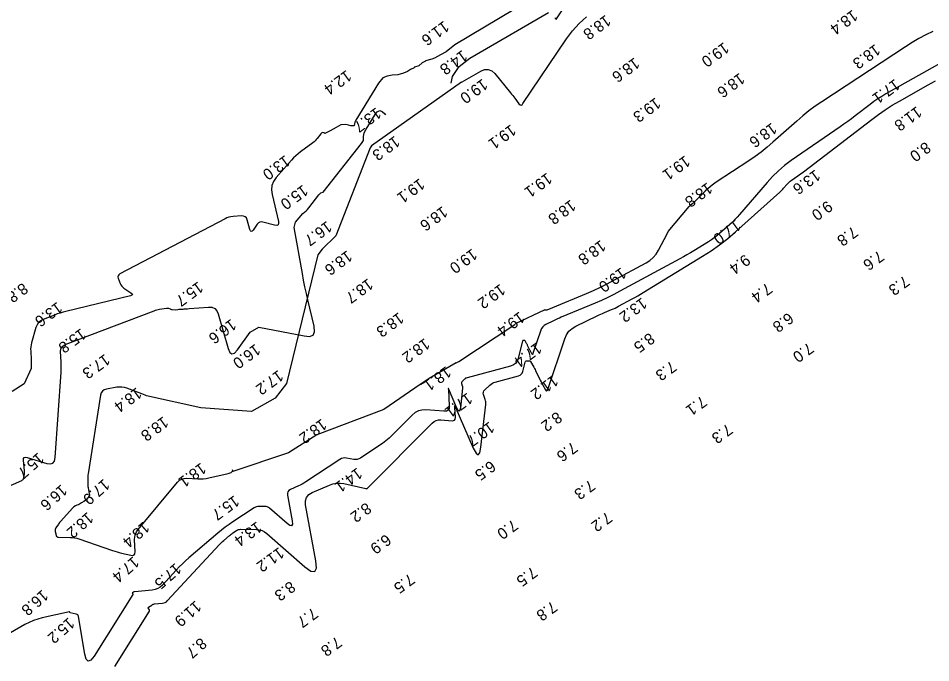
# Model space of a CAD drawing. Extents: x 824616 to 827440, y 158441 to 163197.
# Drawn here: x 825792.9 to 826199.3, y 159276.7 to 159563.5 of the extents above; entities that cross this region are included whole.
import ezdxf

# ---------------------------------------------------------------- set-up
doc = ezdxf.new("R2010")
doc.units = 0
for name, color, linetype in [('V-CHAN-CONT-EL14', 7, 'Continuous'), ('V-CHAN-CONT-EL16', 7, 'Continuous'), ('V-CHAN-CONT-EL18', 7, 'Continuous'), ('V-TOPO-SOUN', 7, 'Continuous')]:
    doc.layers.add(name, color=color, linetype=linetype)

msp = doc.modelspace()

# ---------------------------------------------------------------- linework, layer by layer
at = {"layer": 'V-CHAN-CONT-EL14'}
for points in [[(826013.71, 159567.36), (825987.36, 159551.67), (825983.43, 159548.57), (825981.02, 159547.23), (825979.59, 159546.5), (825978.35, 159545.74), (825977.08, 159545.37), (825974.32, 159544.63), (825974.34, 159544.36), (825972.76, 159543.67), (825971.35, 159542.4), (825969.32, 159541.75), (825969.24, 159541.53), (825967.6, 159540.72), (825966.32, 159539.89), (825964.52, 159539.13), (825961.94, 159538.36), (825959.37, 159538.16), (825957.28, 159537.82), (825955.28, 159536.97), (825953.37, 159534.66), (825943.28, 159518.21), (825942.85, 159517.32), (825942.63, 159516.42), (825942.61, 159516.18), (825942.57, 159515.99), (825942.51, 159515.83), (825942.35, 159515.71), (825942.05, 159515.63), (825941.67, 159515.58), (825940.99, 159515.66), (825940, 159516), (825938.85, 159516.3), (825936.61, 159516.12), (825934.55, 159514.97), (825931.88, 159513.39), (825929.43, 159512.2), (825928.99, 159512.58), (825928.55, 159512.69), (825928.13, 159512.55), (825927.71, 159512.14), (825926.06, 159510.01), (825925.63, 159509.49), (825925.17, 159509.01), (825924.67, 159508.56), (825924.15, 159508.14), (825918.64, 159504.07), (825917.57, 159503.24), (825916.55, 159502.34), (825915.57, 159501.4), (825914.65, 159500.4), (825907.83, 159492.63), (825906.63, 159490.93), (825905.92, 159489.11), (825905.7, 159487.18), (825905.96, 159485.12), (825908.8, 159473.1), (825908.89, 159472.15), (825908.64, 159471.55), (825908.03, 159471.31), (825907.08, 159471.42), (825901.86, 159472.79), (825901.12, 159472.89), (825900.46, 159472.77), (825899.88, 159472.44), (825899.37, 159471.89), (825897.5, 159469.26), (825897.06, 159468.78), (825896.69, 159468.67), (825896.37, 159468.9), (825896.12, 159469.5), (825894.86, 159473.87), (825894.51, 159474.67), (825893.98, 159475.21), (825893.29, 159475.51), (825892.42, 159475.57), (825888.61, 159475.3), (825887.67, 159475.18), (825886.76, 159474.97), (825885.87, 159474.67), (825885.01, 159474.27), (825838.16, 159449.73), (825837.68, 159449.39), (825837.4, 159448.96), (825837.33, 159448.46), (825837.46, 159447.88), (825838.39, 159445.41), (825838.66, 159444.83), (825839.01, 159444.3), (825839.44, 159443.84), (825839.96, 159443.45), (825843.11, 159441.36), (825843.62, 159440.92), (825843.76, 159440.56), (825843.51, 159440.25), (825842.87, 159440.02), (825814.2, 159433.05), (825812.9, 159432.71), (825811.62, 159432.33), (825810.34, 159431.91), (825809.08, 159431.45), (825804.07, 159429.51), (825802.93, 159428.93), (825802, 159428.14), (825801.3, 159427.15), (825800.83, 159425.96), (825798.89, 159419.14), (825798.67, 159418.2), (825798.52, 159417.26), (825798.46, 159416.3), (825798.47, 159415.34), (825798.69, 159411.46), (825798.73, 159410.5), (825798.74, 159409.53), (825798.72, 159408.56), (825798.67, 159407.59), (825795.5, 159400.82), (825790.27, 159397.45)], [(825835.93, 159275.06), (825851.33, 159299.67), (825851.4, 159299.82), (825851.43, 159299.97), (825851.4, 159300.13), (825851.32, 159300.27), (825850.91, 159300.87), (825850.83, 159301.01), (825850.83, 159301.15), (825850.88, 159301.27), (825850.99, 159301.38), (825852.4, 159302.39), (825852.69, 159302.57), (825853, 159302.71), (825853.32, 159302.8), (825853.66, 159302.86), (825857.11, 159303.18), (825857.77, 159303.3), (825858.38, 159303.54), (825858.93, 159303.88), (825859.43, 159304.33), (825882.36, 159329.15), (825882.86, 159329.67), (825883.38, 159330.18), (825883.91, 159330.67), (825884.45, 159331.15), (825887.02, 159333.34), (825887.39, 159333.65), (825887.78, 159333.94), (825888.16, 159334.23), (825888.56, 159334.5), (825890.17, 159335.56), (825890.59, 159335.79), (825891.02, 159335.96), (825891.47, 159336.05), (825891.94, 159336.08), (825898.98, 159336), (825900.27, 159335.88), (825901.48, 159335.54), (825902.61, 159334.99), (825903.65, 159334.22), (825920.6, 159319.39), (825923.27, 159317.49), (825924.97, 159317.31), (825925.68, 159318.85), (825925.42, 159322.12), (825920.9, 159347.03), (825920.82, 159348.81), (825921.28, 159350.31), (825922.27, 159351.52), (825923.8, 159352.45), (825931.48, 159355.79), (825933.04, 159356.33), (825934.64, 159356.62), (825936.26, 159356.64), (825937.9, 159356.41), (825947.77, 159354.23), (825947.81, 159354.22), (825947.85, 159354.21), (825947.89, 159354.2), (825947.93, 159354.19), (825948.18, 159354.15), (825948.18, 159354.15), (825948.18, 159354.15), (825948.18, 159354.15), (825948.19, 159354.15), (825948.2, 159354.16), (825948.2, 159354.16), (825977.32, 159383.38), (825978.13, 159384.05), (825979.03, 159384.51), (825980.01, 159384.75), (825981.07, 159384.78), (825986.12, 159384.41), (825986.79, 159384.45), (825987.26, 159384.71), (825987.53, 159385.17), (825987.59, 159385.85), (825987.34, 159390.33), (825987.34, 159390.42), (825987.33, 159390.52), (825987.33, 159390.61), (825987.32, 159390.7), (825987.3, 159391.07), (825987.3, 159391.14), (825987.31, 159391.16), (825987.33, 159391.14), (825987.36, 159391.08), (825995.56, 159372.19), (825996.78, 159369.91), (825997.76, 159369.23), (825998.49, 159370.16), (825998.98, 159372.71), (826001.07, 159391.61), (826001.1, 159392.19), (826001.08, 159392.76), (826000.99, 159393.33), (826000.84, 159393.9), (826000.12, 159396.14), (826000.02, 159396.68), (826000.07, 159397.18), (826000.27, 159397.64), (826000.62, 159398.07), (826002.92, 159400.24), (826003.47, 159400.69), (826004.06, 159401.07), (826004.69, 159401.38), (826005.37, 159401.6), (826015.67, 159404.36), (826016.38, 159404.64), (826016.94, 159405.07), (826017.36, 159405.63), (826017.63, 159406.34), (826018.7, 159410.53), (826018.78, 159410.74), (826018.92, 159410.9), (826019.1, 159411), (826019.32, 159411.04), (826020.32, 159411.1), (826020.56, 159411.09), (826020.76, 159411.02), (826020.93, 159410.89), (826021.07, 159410.7), (826022.5, 159408.17), (826022.77, 159407.67), (826023.04, 159407.17), (826023.3, 159406.66), (826023.56, 159406.15), (826025.1, 159403.01), (826025.4, 159402.39), (826025.71, 159401.79), (826026.02, 159401.18), (826026.34, 159400.58), (826027.64, 159398.18), (826027.95, 159397.74), (826028.23, 159397.61), (826028.48, 159397.79), (826028.71, 159398.28), (826036.27, 159420.84), (826037.07, 159422.65), (826038.17, 159424.2), (826039.56, 159425.48), (826041.26, 159426.51), (826050.75, 159431.09), (826051.54, 159431.46), (826052.33, 159431.82), (826053.12, 159432.17), (826053.92, 159432.52), (826057.13, 159433.85), (826057.93, 159434.2), (826058.72, 159434.56), (826059.5, 159434.95), (826060.27, 159435.35), (826066.28, 159438.61), (826067.54, 159439.3), (826068.78, 159440), (826070.01, 159440.72), (826071.24, 159441.46), (826097.63, 159457.6), (826101.5, 159460.08), (826105.24, 159462.74), (826108.86, 159465.55), (826112.35, 159468.54), (826132.04, 159486.13), (826132.48, 159486.54), (826132.92, 159486.97), (826133.34, 159487.41), (826133.74, 159487.86), (826135.33, 159489.71), (826135.74, 159490.16), (826136.17, 159490.58), (826136.63, 159490.97), (826137.12, 159491.33), (826140.02, 159493.33), (826140.66, 159493.78), (826141.31, 159494.24), (826141.94, 159494.71), (826142.57, 159495.18), (826172.98, 159518.53), (826175.95, 159520.73), (826178.99, 159522.82), (826182.1, 159524.8), (826185.28, 159526.67), (826198.15, 159533.93), (826201.38, 159535.74)]]:
    msp.add_lwpolyline(points, dxfattribs=at)
at = {"layer": 'V-CHAN-CONT-EL16'}
for points in [[(826031.92, 159563.69), (826032.27, 159563.21), (826032.36, 159563.12), (826032.45, 159563.09), (826032.54, 159563.12), (826032.62, 159563.22), (826036.19, 159568.54)], [(825985.65, 159534.6), (825986.29, 159537.62), (825989.25, 159542.11), (825994.07, 159545.82), (826028.98, 159566.02)], [(826224.18, 159555.16), (826179.28, 159529.82), (826177.47, 159528.75), (826175.7, 159527.63), (826173.98, 159526.44), (826172.29, 159525.2), (826165.64, 159520.09), (826163.96, 159518.82), (826162.27, 159517.57), (826160.57, 159516.35), (826158.85, 159515.15), (826137.13, 159500.17), (826134.2, 159498.01), (826131.43, 159495.67), (826128.81, 159493.16), (826126.36, 159490.47), (826114.07, 159476.15), (826113.06, 159475.01), (826112, 159473.9), (826110.91, 159472.82), (826109.79, 159471.78), (826105.21, 159467.69), (826104.05, 159466.7), (826102.84, 159465.76), (826101.59, 159464.87), (826100.3, 159464.05), (826093.75, 159460.04), (826092.22, 159459.11), (826090.67, 159458.21), (826089.11, 159457.33), (826087.54, 159456.46), (826060.84, 159442), (826058.15, 159440.59), (826055.42, 159439.24), (826052.66, 159437.97), (826049.87, 159436.76), (826034.76, 159430.46), (826033.89, 159430.09), (826033.03, 159429.71), (826032.17, 159429.32), (826031.32, 159428.91), (826027.92, 159427.27), (826027.14, 159426.8), (826026.49, 159426.21), (826025.99, 159425.5), (826025.62, 159424.66), (826022.13, 159414.26), (826022.03, 159414.03), (826021.91, 159413.95), (826021.78, 159414.01), (826021.64, 159414.21), (826021.04, 159415.32), (826020.89, 159415.6), (826020.75, 159415.87), (826020.61, 159416.15), (826020.47, 159416.44), (826019.76, 159417.89), (826019.64, 159418.12), (826019.52, 159418.36), (826019.4, 159418.59), (826019.27, 159418.82), (826018.61, 159419.98), (826018.54, 159420.07), (826018.47, 159420.13), (826018.37, 159420.16), (826018.26, 159420.17), (826017.8, 159420.14), (826017.7, 159420.12), (826017.62, 159420.08), (826017.55, 159420), (826017.52, 159419.9), (826015.52, 159412.12), (826015.06, 159410.9), (826014.35, 159409.93), (826013.39, 159409.21), (826012.18, 159408.73), (825992.76, 159403.53), (825992.45, 159403.42), (825992.15, 159403.28), (825991.88, 159403.11), (825991.63, 159402.9), (825990.57, 159401.9), (825990.41, 159401.7), (825990.32, 159401.49), (825990.29, 159401.26), (825990.34, 159401.01), (825990.67, 159399.97), (825990.74, 159399.72), (825990.78, 159399.45), (825990.79, 159399.19), (825990.78, 159398.92), (825989.82, 159390.21), (825989.59, 159389.04), (825989.25, 159388.61), (825988.8, 159388.92), (825988.24, 159389.97), (825984.46, 159398.68), (825984.44, 159398.71), (825984.43, 159398.72), (825984.43, 159398.7), (825984.43, 159398.67), (825984.44, 159398.5), (825984.44, 159398.46), (825984.45, 159398.42), (825984.45, 159398.37), (825984.45, 159398.33), (825984.85, 159390.92), (825984.75, 159389.84), (825984.33, 159389.09), (825983.57, 159388.68), (825982.49, 159388.6), (825974.39, 159389.2), (825972.69, 159389.16), (825971.11, 159388.77), (825969.67, 159388.03), (825968.35, 159386.95), (825959.42, 159377.98), (825958.04, 159376.67), (825956.6, 159375.43), (825955.09, 159374.26), (825953.53, 159373.17), (825945.31, 159367.76), (825944.61, 159367.39), (825943.89, 159367.16), (825943.13, 159367.09), (825942.35, 159367.17), (825939.15, 159367.78), (825938.36, 159367.86), (825937.61, 159367.78), (825936.88, 159367.56), (825936.19, 159367.19), (825920.97, 159357.16), (825920.17, 159356.66), (825919.35, 159356.19), (825918.51, 159355.76), (825917.66, 159355.37), (825914.2, 159353.86), (825913.46, 159353.41), (825912.98, 159352.83), (825912.76, 159352.11), (825912.8, 159351.25), (825914.87, 159339.86), (825914.99, 159338.36), (825914.66, 159337.65), (825913.88, 159337.73), (825912.65, 159338.6), (825904.84, 159345.43), (825904.36, 159345.79), (825903.84, 159346.04), (825903.29, 159346.2), (825902.69, 159346.25), (825900.23, 159346.28), (825899.63, 159346.25), (825899.06, 159346.12), (825898.51, 159345.91), (825897.98, 159345.62), (825888.54, 159339.4), (825886.81, 159338.22), (825885.13, 159336.99), (825883.48, 159335.72), (825881.87, 159334.39), (825868.92, 159323.36), (825867.45, 159322.07), (825866.02, 159320.73), (825864.63, 159319.35), (825863.27, 159317.93), (825857.12, 159311.28), (825856.15, 159310.39), (825855.07, 159309.72), (825853.88, 159309.27), (825852.59, 159309.03), (825844.75, 159308.3), (825844.63, 159308.28), (825844.51, 159308.24), (825844.4, 159308.19), (825844.3, 159308.13), (825843.79, 159307.76), (825843.75, 159307.72), (825843.73, 159307.68), (825843.73, 159307.63), (825843.76, 159307.58), (825843.91, 159307.36), (825843.93, 159307.31), (825843.95, 159307.25), (825843.94, 159307.2), (825843.91, 159307.14), (825826.74, 159279.7), (825825.29, 159277.86), (825824.12, 159277.38), (825823.22, 159278.27), (825822.59, 159280.53), (825819.79, 159297.25), (825819.66, 159297.67), (825819.44, 159297.99), (825819.13, 159298.23), (825818.72, 159298.38), (825816.11, 159298.97), (825816.06, 159298.99), (825816.01, 159299.02), (825815.98, 159299.06), (825815.96, 159299.11), (825815.9, 159299.34), (825815.87, 159299.39), (825815.84, 159299.42), (825815.8, 159299.43), (825815.75, 159299.43), (825803.63, 159296.68), (825801.62, 159296.15), (825799.66, 159295.47), (825797.76, 159294.66), (825795.91, 159293.69), (825784.78, 159287.37)], [(825945.71, 159507.78), (825946.6, 159509.14), (825946.61, 159510.88), (825947.02, 159512.58), (825947.82, 159514.22), (825951.8, 159520.71), (825952.81, 159521.95), (825953.88, 159522.4), (825955, 159522.08), (825956.17, 159520.99), (825956.53, 159520.54)], [(825915.81, 159470.47), (825916.37, 159472.8), (825919.7, 159476.61), (825920.41, 159477.18), (825921.08, 159477.79), (825921.71, 159478.44), (825922.29, 159479.14), (825926.74, 159484.9), (825927.68, 159485.8), (825928.64, 159486.13), (825945.71, 159507.78)], [(825900.11, 159426.08), (825920.25, 159422.14), (825922.7, 159421.84), (825924.26, 159422.46), (825924.91, 159424), (825924.67, 159426.46), (825921.91, 159438.14), (825921.24, 159441.07), (825920.61, 159444), (825920.02, 159446.94), (825919.47, 159449.9), (825915.81, 159470.47)], [(825767.31, 159346), (825794.49, 159357.87), (825794.82, 159358.06), (825795.08, 159358.31), (825795.26, 159358.62), (825795.37, 159358.99), (825795.67, 159360.58), (825795.72, 159360.98), (825795.76, 159361.37), (825795.76, 159361.77), (825795.74, 159362.18), (825795.31, 159366.8), (825795.34, 159367.56), (825795.62, 159368.02), (825796.13, 159368.2), (825796.88, 159368.08), (825805.64, 159365.39), (825807.19, 159365.15), (825808.33, 159365.5), (825809.06, 159366.44), (825809.39, 159367.97), (825812.03, 159406.07), (825812.09, 159407.21), (825812.12, 159408.35), (825812.11, 159409.49), (825812.06, 159410.63), (825811.8, 159415.19), (825811.88, 159416.24), (825812.24, 159417.11), (825812.88, 159417.79), (825813.81, 159418.29), (825853.52, 159433.36), (825854.08, 159433.56), (825854.66, 159433.73), (825855.24, 159433.87), (825855.83, 159433.99), (825858.98, 159434.52), (825859.18, 159434.54), (825859.38, 159434.54), (825859.58, 159434.51), (825859.77, 159434.45), (825860.54, 159434.16), (825860.73, 159434.09), (825860.91, 159433.99), (825861.18, 159433.95), (825861.53, 159433.84), (825862.83, 159433.81), (825864.05, 159433.93), (825864.52, 159434)], [(825864.41, 159434.01), (825864.63, 159433.99), (825865.48, 159434.02), (825866.32, 159434.1), (825866.89, 159434.16), (825867.41, 159434.17), (825867.92, 159434.18), (825868.34, 159434.22), (825869.11, 159434.38), (825877.59, 159434.99), (825879.15, 159434.89), (825880.4, 159434.35), (825881.34, 159433.37), (825881.97, 159431.93), (825886.39, 159416.62), (825887.15, 159414.83), (825888.1, 159414.12), (825889.22, 159414.47), (825890.54, 159415.91), (825896.15, 159423.78), (825900.11, 159426.08)]]:
    msp.add_lwpolyline(points, dxfattribs=at)
at = {"layer": 'V-CHAN-CONT-EL18'}
for p, q in [((826082.27, 159468.59), (826091.68, 159479.75)), ((826027.4, 159433.71), (826014.24, 159427.47))]:
    msp.add_line(p, q, dxfattribs=at)
for points in [[(825990.34, 159535.04), (825990.62, 159535.25), (825998.87, 159540.03), (826000.62, 159540.74), (826002.25, 159540.79), (826003.76, 159540.18), (826005.15, 159538.89), (826012.14, 159530.4), (826012.63, 159529.8), (826013.11, 159529.2), (826013.59, 159528.58), (826014.05, 159527.97), (826015.9, 159525.49), (826016.36, 159525.03), (826016.81, 159524.88), (826017.26, 159525.05), (826017.69, 159525.53), (826036.99, 159554.34), (826039.66, 159557.94), (826042.64, 159561.23), (826045.94, 159564.2)], [(826200.24, 159557.7), (826197.1, 159556.15), (826194.02, 159554.49), (826191, 159552.73), (826188.04, 159550.86), (826150.72, 159526.31), (826147.82, 159524.33), (826145.01, 159522.25), (826142.27, 159520.07), (826139.62, 159517.79), (826128.99, 159508.32), (826126.41, 159506.1), (826123.75, 159503.98), (826121.02, 159501.95), (826118.21, 159500.03), (826103.76, 159490.52), (826102.47, 159489.62), (826101.22, 159488.66), (826100.03, 159487.64), (826098.88, 159486.56), (826094.39, 159482.13), (826093.25, 159481.05), (826092.05, 159480.04), (826091.68, 159479.75)], [(825990.34, 159535.04), (825950.26, 159506.81), (825949.64, 159505.8), (825934.36, 159466.66), (825928.2, 159460.7), (825926.28, 159458.21), (825912.39, 159401), (825907.38, 159394.5), (825896.8, 159388.56), (825874.22, 159390.11), (825850.1, 159395.43)], [(826027.4, 159433.71), (826028.38, 159433.83), (826030.99, 159434.83), (826045.97, 159441.07), (826049.08, 159442.42), (826052.16, 159443.84), (826055.2, 159445.34), (826058.21, 159446.92), (826072.49, 159454.66), (826074.2, 159455.75), (826075.69, 159457.05), (826076.97, 159458.56), (826078.03, 159460.29), (826081.85, 159467.61), (826082.27, 159468.59)], [(825987.88, 159410.24), (825989.07, 159410.83), (826014, 159427.26), (826014.24, 159427.47)], [(825987.88, 159410.24), (825975.89, 159403.21), (825971.87, 159400.47), (825955.74, 159389.45), (825925.95, 159378.18), (825913.29, 159370.06), (825888.08, 159361.67)], [(825972.08, 159400.57), (825972.19, 159400.62), (825975.64, 159402.9), (825975.79, 159403.02)], [(825850.1, 159395.43), (825849.42, 159395.79), (825847.97, 159396.4), (825841.3, 159398.86), (825840.19, 159399.19), (825839.08, 159399.37), (825837.95, 159399.4), (825836.8, 159399.28), (825832.2, 159398.5), (825831.17, 159398.18), (825830.39, 159397.63), (825829.84, 159396.83), (825829.54, 159395.8), (825824.03, 159360.8), (825823.95, 159360.17), (825823.89, 159359.53), (825823.86, 159358.9), (825823.85, 159358.26), (825823.89, 159355.7), (825823.98, 159355.15), (825824.06, 159354.76), (825824.14, 159354.33), (825824.25, 159353.84), (825824.44, 159352.77), (825824.69, 159351.3), (825824.39, 159350.77), (825824.09, 159350.16), (825823.7, 159349.74), (825823.51, 159349.53), (825823.25, 159349.3)], [(825823.26, 159349.31), (825823.06, 159349.1), (825822.81, 159348.87), (825822.17, 159348.52), (825821.16, 159347.81), (825819.82, 159346.92), (825819.06, 159346.77), (825818.36, 159346.49), (825817.73, 159346.09), (825817.16, 159345.56), (825811.93, 159339.77), (825811.63, 159339.42), (825811.34, 159339.07), (825811.06, 159338.7), (825810.8, 159338.32), (825809.73, 159336.74), (825809.53, 159336.38), (825809.41, 159335.99), (825809.37, 159335.59), (825809.42, 159335.17), (825809.76, 159333.46), (825809.89, 159333.09), (825810.11, 159332.82), (825810.41, 159332.65), (825810.8, 159332.59), (825815.99, 159332.51), (825817, 159332.45), (825817.99, 159332.32), (825818.96, 159332.11), (825819.93, 159331.82), (825834.94, 159326.71), (825835.93, 159326.38), (825836.93, 159326.08), (825837.94, 159325.79), (825838.95, 159325.53), (825843.01, 159324.53), (825843.89, 159324.44), (825844.51, 159324.67), (825844.87, 159325.23), (825844.96, 159326.12), (825844.75, 159331.56), (825844.81, 159332.78), (825845.08, 159333.92), (825845.57, 159335), (825846.27, 159336), (825863.9, 159357.07), (825864.75, 159357.89), (825865.71, 159358.45), (825866.77, 159358.76), (825867.95, 159358.82), (825872.87, 159358.55), (825874.1, 159358.52), (825875.32, 159358.58), (825876.54, 159358.72), (825877.75, 159358.95), (825886.38, 159360.85), (825887.81, 159361.35), (825888.43, 159362.07), (825888.32, 159362.55)]]:
    msp.add_lwpolyline(points, dxfattribs=at)

# ---------------------------------------------------------------- texts
at = {"layer": 'V-TOPO-SOUN'}
for s, rotation, p in [('18.8 ', 216.2, (826054.51, 159565.27)), ('18.4 ', 216.2, (826164.45, 159567.53)), ('11.6 ', 216.2, (825982.51, 159562.64)), ('19.0 ', 216.2, (826107.16, 159553.1)), ('18.3 ', 216.2, (826174.51, 159552.26)), ('14.8 ', 216.2, (825990.67, 159549.62)), ('18.6 ', 216.2, (826067.34, 159546.28)), ('12.4 ', 216.2, (825939.09, 159540.71)), ('19.0 ', 216.2, (825999.68, 159536.85)), ('18.6 ', 216.2, (826114.16, 159539.45)), ('17.1 ', 216.2, (826183.27, 159536.75)), ('19.3 ', 216.2, (826076.73, 159528.5)), ('13.7 ', 216.2, (825952.29, 159524.06)), ('11.8 ', 216.2, (826193.01, 159524.61)), ('19.1 ', 216.2, (826012.31, 159516.51)), ('18.6 ', 216.2, (826128.45, 159517.25)), ('18.3 ', 216.2, (825960.6, 159511.44)), ('8.0', 216.2, (826196.96, 159508.79)), ('13.0 ', 216.2, (825911.76, 159502.82)), ('19.1 ', 216.2, (826089.83, 159502.67)), ('13.6 ', 216.2, (826147.83, 159496.4)), ('19.1 ', 216.2, (825971.64, 159492.48)), ('19.1 ', 216.2, (826028.37, 159495.01)), ('15.0 ', 216.2, (825919.71, 159489.65)), ('18.8 ', 216.2, (826099.77, 159490.68)), ('18.8 ', 216.2, (826038.92, 159483.01)), ('18.6 ', 216.2, (825981.84, 159480.13)), ('9.0', 216.2, (826153.21, 159482.61)), ('16.7 ', 216.2, (825930.37, 159473.53)), ('17.0 ', 216.2, (826112.42, 159474.15)), ('7.8', 216.2, (826164.53, 159471.2)), ('18.8 ', 216.2, (826052.26, 159465.05)), ('18.6 ', 216.2, (825939.4, 159460.45)), ('19.0 ', 216.2, (825995.03, 159461.22)), ('7.6', 216.2, (826176.14, 159460.42)), ('9.4', 216.2, (826116.59, 159458.75)), ('19.0 ', 216.2, (826061.39, 159452.86)), ('15.7 ', 216.2, (825873.05, 159446.6)), ('18.7 ', 216.2, (825948.68, 159447.96)), ('7.3', 216.2, (826187.48, 159449.25)), ('8.8', 216.2, (825794.96, 159446.04)), ('19.2 ', 216.2, (826007.55, 159445.52)), ('7.4', 216.2, (826126.34, 159446)), ('13.2 ', 216.2, (826070.63, 159439.46)), ('13.6 ', 216.2, (825810.34, 159437.51)), ('18.3 ', 216.2, (825962.36, 159432.89)), ('19.4 ', 216.2, (826016.15, 159433.2)), ('6.8', 216.2, (826135.84, 159432.81)), ('16.6 ', 216.2, (825887.74, 159429.94)), ('15.8 ', 216.2, (825820.87, 159425.77)), ('8.5', 216.2, (826074.01, 159423.8)), ('16.0 ', 216.2, (825898.51, 159418.85)), ('18.2 ', 216.2, (825973.92, 159421.38)), ('17.4 ', 216.2, (826023.78, 159419.48)), ('7.0', 216.2, (826144.79, 159419.45)), ('17.3 ', 216.2, (825831.51, 159414.35)), ('7.3', 216.2, (826083.72, 159411.28)), ('17.2 ', 216.2, (825908.73, 159407.2)), ('18.1 ', 216.2, (825983.45, 159408.89)), ('11.2 ', 216.2, (826031.16, 159405.02)), ('18.4 ', 216.2, (825845.66, 159399.46)), ('17.1 ', 216.2, (825992.93, 159397.09)), ('7.1', 216.2, (826097.23, 159395.7)), ('18.8 ', 216.2, (825857.55, 159386.59)), ('18.2 ', 216.2, (825928.04, 159385.53)), ('8.2', 216.2, (826032.78, 159388.7)), ('10.7 ', 216.2, (826002.72, 159384.25)), ('7.3', 216.2, (826108.7, 159383.31)), ('7.6', 216.2, (826039.67, 159375.27)), ('15.7 ', 221.4, (825801.8, 159370.55)), ('18.1 ', 216.2, (825874.34, 159365.98)), ('6.5', 216.2, (826003.24, 159366.93)), ('14.1 ', 216.2, (825943.87, 159363.76)), ('17.9 ', 221.4, (825831, 159358.83)), ('7.3', 216.2, (826047.5, 159358.39)), ('16.6 ', 221.4, (825812.07, 159356.31)), ('15.7 ', 216.2, (825889.13, 159351.42)), ('8.2', 216.2, (825947.86, 159348.25)), ('18.2 ', 221.4, (825823.76, 159344.04)), ('7.2', 216.2, (826055.07, 159344.1)), ('18.4 ', 221.4, (825848.73, 159339.81)), ('13.4 ', 216.2, (825899.18, 159339.8)), ('7.0', 216.2, (826013.13, 159340.71)), ('6.9', 216.2, (825956.68, 159334.18)), ('11.2 ', 216.2, (825909.05, 159328.37)), ('17.4 ', 221.4, (825844.1, 159324.32)), ('17.5 ', 221.4, (825862.87, 159321.35)), ('7.5', 216.2, (825967.16, 159316.64)), ('7.5', 216.2, (826021.76, 159319.73)), ('8.3', 216.2, (825914.05, 159313.27)), ('16.8 ', 221.4, (825803.65, 159309.52)), ('11.9 ', 221.4, (825871.82, 159304.62)), ('7.7', 216.2, (825924.07, 159301.45)), ('7.8', 216.2, (826030.64, 159304.39)), ('15.2 ', 221.4, (825815.36, 159297.16)), ('7.8', 216.2, (825934.7, 159288.62)), ('8.7', 221.4, (825874.14, 159288.17))]:
    msp.add_text(s, height=5, rotation=rotation, dxfattribs=at).set_placement(p)

doc.saveas('drawing.dxf')
